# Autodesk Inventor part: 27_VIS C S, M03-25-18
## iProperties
Created: 2002-07
Part Number: 27_VIS C S, M03-25-18
Material: C35
Document SubType Name: Modélisation
Designer: FIEVET
Company: Lycée Joliot Curie
Control State: 0
Master: False
Checked Out: False
Shininess: 20.0
Length Units: 11269
Angle Units: 11279
Time Units: 11290
Mass Units: 11283
Length Display Precision: 3
Angle Display Precision: 2
Compacted: True
Density: 0.0
Volumn: 0.0
Area: 0.0
PropertySet Name: Model Information
Title: Vis CS
Subject: NF EN ISO 1207
Author: FIEVET
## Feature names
1. Révolution1 [Revolution]
2. Chanfrein1 [Chamfer]
3. Extrusion1
